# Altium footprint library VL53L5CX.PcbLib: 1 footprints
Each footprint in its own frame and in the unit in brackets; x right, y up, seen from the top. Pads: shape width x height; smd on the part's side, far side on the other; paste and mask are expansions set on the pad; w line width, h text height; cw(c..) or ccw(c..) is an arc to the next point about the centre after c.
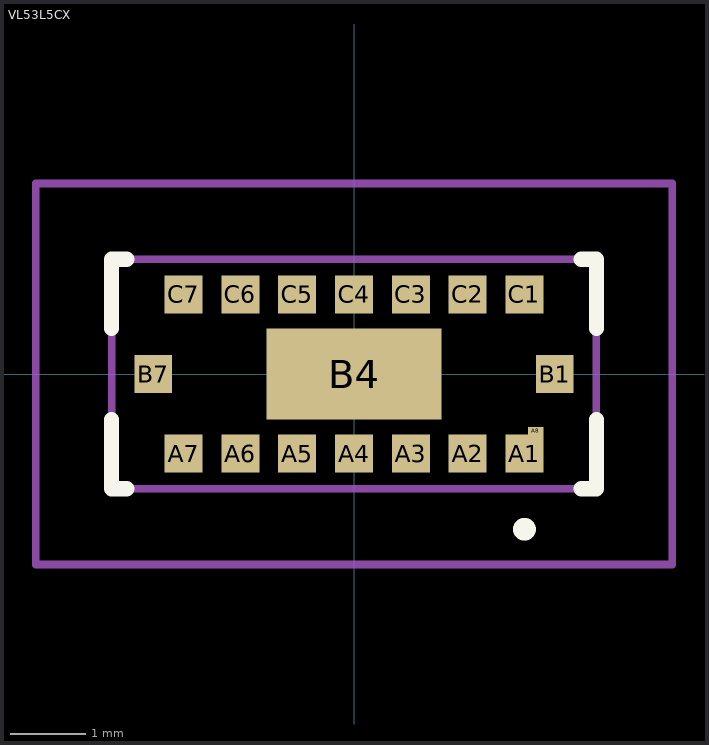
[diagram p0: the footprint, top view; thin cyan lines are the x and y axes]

## VL53L5CX [mm]
pads (18):
  rect 0.5x0.5 smd: A1(2.25,-1.05) A2(1.5,-1.05) A3(0.75,-1.05) A4(0,-1.05) A5(-0.75,-1.05) A6(-1.5,-1.05) A7(-2.25,-1.05) B1(2.65,0) B7(-2.65,0) C1(2.25,1.05) C2(1.5,1.05) C3(0.75,1.05) C4(0,1.05) C5(-0.75,1.05) C6(-1.5,1.05) C7(-2.25,1.05)
  rect 0.2x0.1 smd: A8(2.4,-0.75)
  rect 2.316x1.2 smd: B4(0,0)
Top Overlay:
  lines w0.2: -3.2,-0.6 -3.2,-1.515 -3,-1.515 ; -3.2,0.6 -3.2,1.515 -3,1.515 ; 3,-1.515 3.2,-1.515 3.2,-0.6 ; 3,1.515 3.2,1.515 3.2,0.6 ; 2.25,-2.1 2.25,-2.1 ; 2.25,-2.1 ccw(c2.25,-2.05) 2.25,-2 ; 2.25,-2.1 cw(c2.25,-2.05) 2.25,-2 ; 2.25,-2.1 2.25,-2 ; 2.25,-2 2.25,-2
Mechanical 15:
  lines w0.1: -3.2,-1.515 3.2,-1.515 3.2,1.515 -3.2,1.515 -3.2,-1.515
Mechanical 20:
  lines w0.1: -4.2,-2.515 4.2,-2.515 4.2,2.515 -4.2,2.515 -4.2,-2.515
